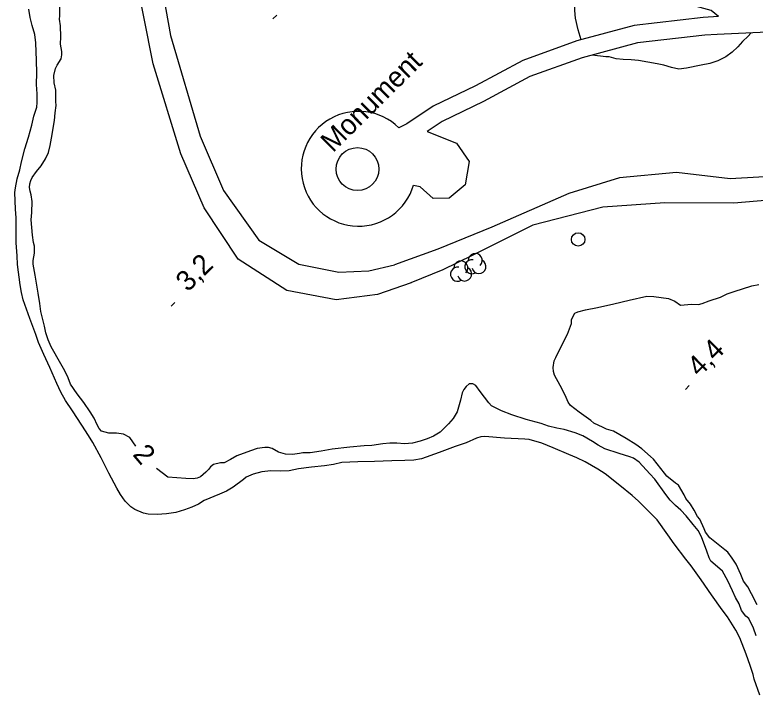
# Model space of a CAD drawing. Extents: x 381879 to 384696, y 5564785 to 5567594.
# Drawn here: x 382445.1 to 382555, y 5565640.1 to 5565741.1 of the extents above; entities that cross this region are included whole.
import ezdxf

# ---------------------------------------------------------------- set-up
doc = ezdxf.new("R2010")
doc.units = 0
for name, color, linetype in [('Niveau 2', 7, 'Continuous'), ('Niveau 22', 7, 'Continuous'), ('Niveau 3', 7, 'Continuous'), ('Niveau 36', 7, 'Continuous'), ('Niveau 39', 7, 'Continuous'), ('Niveau 4', 7, 'Continuous'), ('Niveau 44', 7, 'Continuous')]:
    doc.layers.add(name, color=color, linetype=linetype)

msp = doc.modelspace()

# ---------------------------------------------------------------- linework, layer by layer
at = {"layer": 'Niveau 2'}
for points in [[(382529.19, 5565737.38), (382528.76, 5565738.84), (382528.37, 5565740.61), (382528.25, 5565741.75), (382528.23, 5565743.36), (382528.31, 5565744.41), (382528.13, 5565745.54), (382527.68, 5565746.93)], [(382449.72, 5565693.87), (382449.5, 5565694.9), (382448.98, 5565697.05), (382448.84, 5565698.24), (382448.58, 5565699.78), (382448.15, 5565702.46), (382447.83, 5565704.06), (382447.84, 5565704.63), (382448.02, 5565705.7), (382448.04, 5565706.76), (382447.89, 5565707.3), (382447.75, 5565708.37), (382447.53, 5565710.66), (382447.66, 5565711.75), (382447.67, 5565713.37), (382447.54, 5565714.39), (382447.37, 5565714.9), (382447.31, 5565715.46), (382447.35, 5565715.98), (382447.48, 5565716.48), (382447.7, 5565716.93), (382448.31, 5565717.85), (382449.03, 5565718.67), (382449.65, 5565719.69), (382450.09, 5565720.63), (382450.36, 5565721.7), (382450.54, 5565722.76), (382451.02, 5565725.42), (382451.1, 5565726.52), (382451.26, 5565727.61), (382451.22, 5565728.23), (382451.2, 5565729.91), (382450.96, 5565730.98), (382450.91, 5565732.09), (382451.14, 5565733.12), (382451.39, 5565733.63), (382451.98, 5565734.57), (382452.09, 5565735.14), (382452.08, 5565735.66), (382451.9, 5565736.71), (382451.93, 5565737.83), (382451.9, 5565739.43), (382451.76, 5565740.44), (382451.79, 5565740.95), (382451.81, 5565743.66)], [(382554.38, 5565738.38), (382553.97, 5565737.9), (382553.17, 5565737.14), (382552.48, 5565736.33), (382551.63, 5565735.53), (382550.67, 5565734.85), (382549.5, 5565734.26), (382548.29, 5565733.84), (382546.99, 5565733.6), (382544.84, 5565733.15), (382543.71, 5565733.04), (382542.61, 5565733.26), (382541.49, 5565733.6), (382540.46, 5565733.82)], [(382540.46, 5565733.82), (382537.7, 5565734.32), (382536.6, 5565734.42), (382535.44, 5565734.43), (382534.38, 5565734.54), (382533.35, 5565734.85), (382532.84, 5565734.86), (382530.81, 5565735.11)], [(382555.34, 5565653.53), (382554.5, 5565655.14), (382553.95, 5565656.19), (382553.32, 5565657.02), (382552.9, 5565658.03), (382552.19, 5565659.56), (382551.62, 5565660.47), (382550.96, 5565661.35), (382550.53, 5565661.68), (382548.28, 5565663.45), (382547.65, 5565664.32), (382547.46, 5565664.82), (382546.8, 5565666.26), (382546.45, 5565666.66), (382545.99, 5565667.6), (382545.44, 5565668.47), (382544.74, 5565669.31), (382544.5, 5565669.87), (382543.64, 5565671.28), (382543.19, 5565671.6), (382541.89, 5565672.6), (382541.59, 5565673.06), (382539.95, 5565675.16), (382539.47, 5565675.52), (382538.22, 5565676.67), (382537.3, 5565677.31), (382535.87, 5565678.22), (382534, 5565679.3), (382532.98, 5565679.61), (382532.48, 5565679.84), (382531.09, 5565680.51), (382530.63, 5565680.89), (382528.9, 5565682.13), (382527.61, 5565683.12), (382527.27, 5565683.58), (382526.81, 5565684.62), (382526.07, 5565686.09), (382525.23, 5565687.63), (382525.08, 5565688.15), (382525.05, 5565688.75), (382525.21, 5565689.74), (382525.43, 5565690.22), (382526.4, 5565692.24), (382527.17, 5565693.71), (382527.74, 5565695.28), (382527.78, 5565695.87), (382528.25, 5565696.83), (382528.72, 5565697.03), (382529.84, 5565697.3), (382531.62, 5565697.66), (382534.05, 5565698.2), (382536.33, 5565698.76), (382538.97, 5565699.32), (382539.97, 5565699.26), (382542.16, 5565698.99), (382543.11, 5565698.61), (382543.95, 5565698.02), (382544.48, 5565698.03), (382545.56, 5565698.13), (382546.62, 5565698.12), (382547.14, 5565698.23), (382548.21, 5565698.62), (382549.9, 5565699.18), (382550.88, 5565699.67), (382551.9, 5565700.05), (382554.51, 5565700.89), (382555.59, 5565701.06)], [(382463.06, 5565677.08), (382462.17, 5565678.38), (382461.25, 5565678.86), (382460.19, 5565679), (382459.07, 5565679.02), (382457.99, 5565679.31), (382457.65, 5565679.68), (382457.35, 5565680.22), (382456.88, 5565681.22), (382456.31, 5565682.18), (382455.36, 5565683.57), (382454.36, 5565684.82), (382453.39, 5565686.26), (382453.02, 5565687.23), (382452.54, 5565688.24), (382451.95, 5565689.27), (382450.52, 5565691.81), (382450.08, 5565692.84), (382449.72, 5565693.87)], [(382547.06, 5565663.62), (382546.55, 5565664.57), (382545.82, 5565665.43), (382544.78, 5565666.74), (382543.99, 5565667.57), (382543.18, 5565668.28), (382542.43, 5565669.04), (382541.78, 5565669.91), (382540.11, 5565672.2), (382539.38, 5565672.97), (382537.83, 5565674.72), (382536.96, 5565675.31), (382536.41, 5565675.5), (382534.83, 5565675.99), (382532.71, 5565676.69), (382531.73, 5565677.2), (382530.89, 5565677.79), (382529.43, 5565678.63), (382528.32, 5565679.05), (382526.67, 5565679.56), (382525.58, 5565679.75), (382524.36, 5565680.06), (382523.24, 5565680.42), (382521.05, 5565681.04), (382518.88, 5565681.72), (382517.35, 5565682.32), (382515.87, 5565683.08), (382515.48, 5565683.51), (382514.19, 5565685.18), (382513.56, 5565686.07), (382513.09, 5565686.31), (382512.58, 5565686.3), (382512.12, 5565685.93), (382511.77, 5565685.46), (382511.55, 5565684.99), (382511.28, 5565683.9), (382510.78, 5565682.18), (382510.2, 5565681.18), (382509.5, 5565680.41), (382508.25, 5565679.14), (382507.29, 5565678.56), (382506.33, 5565678.16), (382505.27, 5565677.81), (382504.13, 5565677.52), (382502.96, 5565677.4), (382501.85, 5565677.51), (382500.77, 5565677.51), (382499.75, 5565677.42), (382498.1, 5565677.19), (382496.96, 5565677.12), (382494.83, 5565676.93), (382492.23, 5565676.63), (382490.61, 5565676.34), (382488.97, 5565676.1), (382487.88, 5565676.08), (382487.38, 5565675.97), (382486.34, 5565675.85), (382485.28, 5565675.9), (382484.26, 5565676.2), (382483.33, 5565676.75), (382482.77, 5565676.87), (382482.25, 5565676.87), (382481.1, 5565676.72), (382480.12, 5565676.39), (382478.06, 5565675.64), (382477.13, 5565675.09), (382476.18, 5565674.6), (382475.63, 5565674.6), (382474.6, 5565674.37), (382474.15, 5565674.03), (382473.87, 5565673.6), (382473.49, 5565673.2), (382472.66, 5565672.5), (382472.18, 5565672.31), (382471.61, 5565672.25), (382470.51, 5565672.29), (382467.84, 5565672.49), (382466.13, 5565673.75)], [(382548.46, 5565659.99), (382548.18, 5565660.52), (382547.83, 5565661.49), (382547.06, 5565663.62)], [(382555.19, 5565648.92), (382554.76, 5565650.05), (382554.07, 5565651.49), (382553.64, 5565651.84), (382553.02, 5565652.7), (382552.63, 5565653.7), (382552.11, 5565654.62), (382551.67, 5565655.59), (382550.98, 5565657.07), (382550.17, 5565658.53), (382549.77, 5565658.85), (382548.46, 5565659.99)]]:
    msp.add_lwpolyline(points, dxfattribs=at)
at = {"layer": 'Niveau 22'}
for points in [[(382512.25, 5565750.47), (382503.57, 5565751.14), (382494.33, 5565753.03), (382486.18, 5565755.73), (382477.78, 5565759.55), (382470.68, 5565764.22), (382465.96, 5565768.33), (382465.54, 5565764.94), (382465.28, 5565758.29), (382466.13, 5565749.62), (382468.25, 5565738.01), (382472.63, 5565723.06)], [(382549.58, 5565740.85), (382548.49, 5565741.73), (382539.42, 5565744.27), (382530.9, 5565746.17), (382522.52, 5565748.15), (382515.4, 5565749.77), (382512.25, 5565750.47)], [(382503.96, 5565701.31), (382498.95, 5565699.59), (382492.84, 5565698.77), (382485.49, 5565700.18), (382478.27, 5565704.83), (382473.24, 5565712.43), (382469.78, 5565720.47), (382465.64, 5565733.8), (382462.92, 5565747.58)], [(382549.58, 5565740.85), (382547.33, 5565740.68), (382537.06, 5565739.52), (382528.55, 5565737.21), (382520.52, 5565734.32), (382513.52, 5565730.56), (382507.24, 5565727.52), (382503.3, 5565724.92), (382502.11, 5565724.33)], [(382616.13, 5565740.05), (382605.89, 5565733.79), (382600.27, 5565730.75), (382595.17, 5565728.13), (382588.1, 5565724.11), (382574.69, 5565717.79), (382563.97, 5565714.15), (382551.84, 5565713.14), (382541.61, 5565713.17), (382532.42, 5565712.54), (382522.04, 5565709.86), (382513.02, 5565705.35), (382508.68, 5565703.24), (382503.9, 5565701.29)], [(382549.38, 5565738.14), (382547.56, 5565738.07), (382537.55, 5565736.94), (382529.34, 5565734.71), (382521.59, 5565731.92), (382514.71, 5565728.23), (382508.54, 5565725.24), (382506.32, 5565723.77)], [(382598.96, 5565737.37), (382586.57, 5565736.75), (382575.16, 5565737.42), (382564.64, 5565738.38), (382556.83, 5565738.5), (382549.38, 5565738.14)], [(382603.9, 5565737.24), (382600.98, 5565735.05), (382596.55, 5565732.74), (382591.53, 5565730.12), (382584.78, 5565726.62), (382580.09, 5565723.94), (382571.63, 5565720.04), (382560.69, 5565717.31), (382551.32, 5565716.75), (382543.37, 5565717.7), (382534.87, 5565716.9), (382527.37, 5565714.59), (382515.91, 5565709.56), (382507.94, 5565706.29), (382501.5, 5565703.97)], [(382506.32, 5565723.77), (382510.67, 5565722.06), (382512.58, 5565719.34), (382511.95, 5565715.87), (382509.58, 5565713.87), (382507.21, 5565713.84), (382505.28, 5565715.56), (382504.31, 5565715.78)], [(382472.62, 5565723.09), (382476.09, 5565715.02), (382481.36, 5565707.62), (382487.3, 5565704.1), (382493.21, 5565702.91), (382497.69, 5565703.11), (382501.5, 5565703.97)]]:
    msp.add_lwpolyline(points, dxfattribs=at)
msp.add_arc((382496.15, 5565718.24), 8.52, 45.6251, 343.231, dxfattribs=at)
at = {"layer": 'Niveau 3'}
for p, q in [((382483.44, 5565740.47), (382484.01, 5565741.04)), ((382468.3, 5565697.83), (382468.87, 5565698.4)), ((382544.67, 5565685.49), (382545.24, 5565686.06))]:
    msp.add_line(p, q, dxfattribs=at)
at = {"layer": 'Niveau 36'}
msp.add_circle((382528.75, 5565707.75), 1, dxfattribs=at)
at = {"layer": 'Niveau 39'}
msp.add_circle((382495.98, 5565718.2), 3.18, dxfattribs=at)
at = {"layer": 'Niveau 4'}
for points in [[(382445.87, 5565718.07), (382446.12, 5565719.29), (382446.59, 5565721.22), (382447.12, 5565722.93), (382447.66, 5565724.7), (382447.94, 5565726.06), (382448.36, 5565727.4), (382448.44, 5565728.08), (382448.44, 5565729.35), (382448.35, 5565730.72), (382448.37, 5565732.48), (382448.34, 5565734.31), (382448.23, 5565736.92), (382448.1, 5565738.18), (382447.67, 5565739.52), (382447.39, 5565740.69), (382447.19, 5565741.91)], [(382555.7, 5565640.12), (382554.86, 5565642.49), (382554.73, 5565643.21), (382554.31, 5565644.54), (382553.7, 5565646.21), (382552.74, 5565648.65), (382552.14, 5565649.75), (382550.94, 5565651.73), (382550.15, 5565652.81), (382548.56, 5565655.03), (382547.02, 5565657.22), (382545.54, 5565659.33), (382544.74, 5565660.3), (382543, 5565662.57), (382542.04, 5565663.94), (382540.48, 5565666.14), (382539.51, 5565667.14), (382537.7, 5565668.93), (382536.75, 5565669.74), (382534.93, 5565671.24), (382532.74, 5565672.98), (382531.65, 5565673.66), (382529.8, 5565674.74), (382528.55, 5565675.34), (382527.35, 5565675.83), (382525.05, 5565676.83), (382523.36, 5565677.51), (382521.5, 5565678.07), (382520.83, 5565678.11), (382517.81, 5565678.25), (382514.9, 5565678.5), (382514.29, 5565678.48), (382513.67, 5565678.25), (382512.12, 5565677.59), (382510.49, 5565677), (382508.11, 5565676.13), (382505.5, 5565675.18), (382504.33, 5565674.99), (382503, 5565674.94), (382501.07, 5565674.91), (382498.49, 5565674.79), (382496.02, 5565674.73), (382493.67, 5565674.63), (382492.43, 5565674.35), (382491.07, 5565674.15), (382489.15, 5565673.95), (382487.22, 5565673.69), (382485.84, 5565673.43), (382484.49, 5565673.36), (382483.14, 5565673.43), (382481.77, 5565673.25), (382480.52, 5565672.94), (382479.46, 5565672.49), (382479.04, 5565672.15), (382477.54, 5565671), (382476.54, 5565670.42), (382475.51, 5565669.97), (382473.23, 5565669.03), (382472.37, 5565668.48), (382471.4, 5565668), (382470.3, 5565667.61), (382469.01, 5565667.22), (382467.61, 5565667.04), (382466.24, 5565666.93), (382464.9, 5565666.97), (382464.22, 5565667.15), (382462.94, 5565667.67), (382462.33, 5565668.09), (382461.48, 5565668.9), (382460.8, 5565669.89), (382460.27, 5565670.85), (382459.08, 5565673.06), (382457.91, 5565675.34), (382456.7, 5565677.63), (382456.05, 5565678.68), (382455.06, 5565680.18), (382453.7, 5565682.31), (382452.65, 5565683.86), (382451.93, 5565685.09), (382451.36, 5565686.39), (382450.33, 5565688.77), (382449.42, 5565690.68), (382448.65, 5565692.45), (382448.21, 5565693.65), (382447.34, 5565696.02), (382446.36, 5565698.77), (382446.1, 5565699.86), (382445.91, 5565701.01), (382445.51, 5565704.01), (382445.45, 5565705.31), (382445.31, 5565707.25), (382445.32, 5565708.34), (382445.32, 5565710.96), (382445.23, 5565712.22), (382445.11, 5565714.72), (382445.21, 5565715.42), (382445.48, 5565716.74), (382445.87, 5565718.07)]]:
    msp.add_lwpolyline(points, dxfattribs=at)
at = {"layer": 'Niveau 44'}
for centre, start_param, end_param in [((382513.46, 5565704.62), 6.029005, 9.968014), ((382511.34, 5565703.51), 6.029005, 9.968014), ((382512.97, 5565703.7), 1.88946, 5.776035), ((382514.01, 5565703.74), 3.902388, 7.872264), ((382510.85, 5565702.59), 1.88946, 5.776035), ((382511.89, 5565702.63), 3.902388, 7.872264)]:
    msp.add_ellipse(centre, major_axis=(0.912, -0.513), ratio=0.999925, start_param=start_param, end_param=end_param, dxfattribs=at)

# ---------------------------------------------------------------- texts
at = {"layer": 'Niveau 2'}
msp.add_text('2', height=3, rotation=310.3213, dxfattribs=at).set_placement((382462.5, 5565675.79))
at = {"layer": 'Niveau 3'}
for s, p in [('3,2', (382470.81, 5565699.85)), ('4,4', (382546.73, 5565687.22))]:
    msp.add_text(s, height=3, rotation=44.7717, dxfattribs=at).set_placement(p)
at = {"layer": 'Niveau 39'}
msp.add_text('Monument', height=3, rotation=44.7717, dxfattribs=at).set_placement((382492.33, 5565720.53))

doc.saveas('drawing.dxf')
